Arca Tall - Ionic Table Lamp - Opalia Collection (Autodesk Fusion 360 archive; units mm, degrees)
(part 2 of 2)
create_component "CreateComponent4"
create_component "CreateComponent5"
create_component "CreateComponent6"
create_component "CreateComponent7"
create_component "CreateComponent8"
remove_body "RemoveBody1"
create_component "CreateComponent9"
create_component "CreateComponent10"
create_component "CreateComponent11"
create_component "CreateComponent12"
create_component "CreateComponent13"
create_component "CreateComponent14"
create_component "CreateComponent15"
create_component "CreateComponent16"
create_component "CreateComponent17"
create_component "CreateComponent18"
remove_body "RemoveBody6"
create_component "CreateComponent19"
create_component "CreateComponent20"
create_component "CreateComponent21"
create_component "CreateComponent22"
create_component "CreateComponent23"
named bodies: "Marble Base", "Rotary Switch", "Coiled - SVT (Blk Fabric)", "Glass Globe", "Metal Housing", "Metal Socket Cover", "Porcelain Socket", "Brass Dial - Dimmer Knob", "Solitaire Petite", "Facet Petite", "Body1", "Body2", "Plastic Insert", "Silicone Gasket", "Oculo Petite", "Balon v2", "Balon v3", "Trove - TL", "Trove - TL (1)", "Neoprene Pad", "2-Pole Plug End", "Rubber Grommet", "Chinois"

design "Trove - TL"
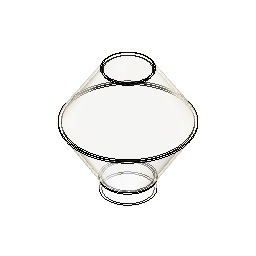
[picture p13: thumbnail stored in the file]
derived_base_feature "Derived Base Feature" bodies "Trove"
hole "Hole1" HoleDepth 88.9 HoleDiameter 44.45 TipAngle 118
sketch "Sketch1" plane through (0, 0, 0) normal (1, 0, 0) x axis (0, 1, 0)
  line L1 (0, 243.0601) -> (0, 247.8226)
  line L2 (-50.8, -12.7122) -> (-50.8, 10.9447)
  line L3 (0, -25.4) -> (0, 243.0601)
  line L4 (-46.0375, -12.7122) -> (-50.8, -12.7122)
  line L5 (-46.0375, -12.7122) -> (-46.0375, 12.3043)
  line L6 (-45.9716, 247.8226) -> (0, 247.8226)
  line L7 (-43.3841, 243.0601) -> (0, 243.0601)
  line L8 (-122.8321, 128.6352) -> (-51.757, 14.2971)
  line L9 (-117.1907, 128.5808) -> (-46.9945, 15.6567)
  line L10 (-48.6353, 246.3754) -> (-122.7993, 132.0392)
  line L11 (-46.0478, 241.6129) -> (-117.1579, 131.9848)
  arc A1 centre (-57.15, 10.9447) radius 6.35 clockwise from (-51.757, 14.2971) to (-50.8, 10.9447)
  arc A2 centre (-52.3875, 12.3043) radius 6.35 clockwise from (-46.9945, 15.6567) to (-46.0375, 12.3043)
  arc A3 centre (-114.4942, 130.257) radius 3.175 between (-117.1579, 131.9848) and (-117.1907, 128.5808)
  arc A4 centre (-120.1356, 130.3114) radius 3.175 between (-122.7993, 132.0392) and (-122.8321, 128.6352)
  arc A5 centre (-45.9716, 244.6476) radius 3.175 between (-45.9716, 247.8226) and (-48.6353, 246.3754)
  arc A6 centre (-43.3841, 239.8851) radius 3.175 clockwise from (-46.0478, 241.6129) to (-43.3841, 243.0601)
  point P3 (0, 247.8226)
  point P4 (0, 243.0601)
  vertical L1
  vertical L3
  tangent L5 A2
  perpendicular L1 L6
  perpendicular L1 L7
  tangent L11 A3
  tangent L9 A3
  tangent L10 A4
  tangent L8 A4
  equal A3 A4
  tangent L6 A5
  tangent L10 A5
  tangent L11 A6
  tangent L7 A6
  dimension "d8" distance P3 P4 = 4.7625
  dimension "d11" radius A2 = 6.35
  dimension "d15" radius A3 = 3.175
  dimension "d16" radius A5 = 3.175
  dimension "d17" radius A6 = 3.175
revolve "Revolve1" sketch "Sketch1" AlongAngle 180 bodies "Trove - TL"
revolve "Revolve2" sketch "Sketch1" AlongAngle -180
component_from_bodies "Body->Comp"
remove_body "RemoveBody2"
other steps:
base_feature "Base Feature" bodies "Trove - TL"
create_component "CreateComponent1"
remove_body "RemoveBody1"
named bodies: "Trove", "Trove - TL"

design "T9-5In"
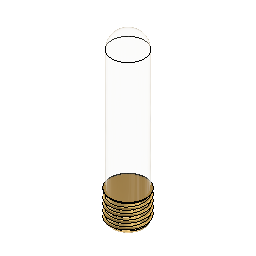
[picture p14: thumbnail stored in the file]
sketch "Sketch1" plane through (0, 0, 0) normal (0, 1, 0) x axis (1, 0, 0)
  line L1 (0, 0) -> (0, -127)
  line L2 (12.7, -127) -> (-12.7, -127)
  line L3 (12.7, -12.7) -> (12.7, -127)
  line L4 (-12.7, -127) -> (-12.7, -12.7)
  arc A1 centre (0, -12.7) radius 12.7 clockwise from (-12.7, -12.7) to (12.7, -12.7)
  point P1 (0, 0)
  point P3 (0, 0)
  coincident P1 P3
  vertical L1
  horizontal L2
  vertical L3
  vertical L4
revolve "Revolve1" sketch "Sketch1" AlongAngle 360 bodies "BU-T10-5-LED-120V"
derived_base_feature "Derived Base Feature" bodies "E26 Base"
move "Move1"
component_from_bodies "Body->Comp"
copy_paste "CutPaste"
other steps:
base_feature "Base Feature" bodies "BU-T10-5-LED-120V"
create_component "CreateComponent1"
create_component "CreateComponent2"
remove_body "RemoveBody1"
remove_instance "RemoveInstance1"
named bodies: "BU-T10-5-LED-120V", "E26 Base"

design "Balon v2"
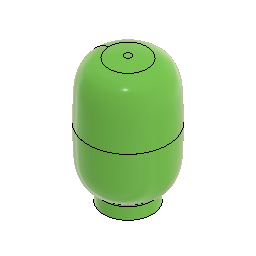
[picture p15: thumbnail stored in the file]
derived_base_feature "Derived Base Feature" bodies "Balon"
work_plane "WorkPlane1" AlongDistance 0
sketch "Sketch1" plane through (0, 0, 0) normal (0, 1, 0) x axis (1, 0, 0)
  line L1 (0, 317.5) -> (0, 2.9083)
  curve K1 (-82.9821, 124.2212) -> (-50.8, 237.8015)
  curve K2 (-51.0925, 237.681) -> (-50.8, 237.8015)
  curve K3 (-51.3855, 237.5558) -> (-51.0925, 237.681)
  curve K4 (-54.7608, 236.0513) -> (-51.3855, 237.5558)
  curve K5 (-57.9615, 234.05) -> (-54.7608, 236.0513)
  curve K6 (-67.2727, 226.749) -> (-57.9615, 234.05)
  curve K7 (-69.0552, 224.2615) -> (-67.2727, 226.749)
  curve K8 (-72.1872, 218.7832) -> (-69.0552, 224.2615)
  curve K9 (-74.1213, 215.1556) -> (-72.1872, 218.7832)
  curve K10 (-78.3031, 204.3965) -> (-74.1213, 215.1556)
  curve K11 (-79.7275, 197.3397) -> (-78.3031, 204.3965)
  curve K12 (-81.3333, 185.4664) -> (-79.7275, 197.3397)
  curve K13 (-81.6254, 178.4008) -> (-81.3333, 185.4664)
  curve K14 (-82.49, 152.2133) -> (-81.6254, 178.4008)
  curve K15 (-82.9821, 136.067) -> (-82.49, 152.2133)
  curve K16 (-82.9821, 124.2212) -> (-82.9821, 136.067)
  curve K17 (50.8, 237.7999) -> (82.9821, 124.2212)
  curve K18 (82.9821, 140.3031) -> (82.9821, 124.2212)
  curve K19 (81.9353, 169.4257) -> (82.9821, 140.3031)
  curve K20 (81.3621, 183.6489) -> (81.9353, 169.4257)
  curve K21 (80.9478, 189.8724) -> (81.3621, 183.6489)
  curve K22 (77.8147, 206.9858) -> (80.9478, 189.8724)
  curve K23 (74.9652, 213.2153) -> (77.8147, 206.9858)
  curve K24 (69.4688, 224.1531) -> (74.9652, 213.2153)
  curve K25 (67.2512, 226.458) -> (69.4688, 224.1531)
  curve K26 (61.5696, 231.3138) -> (67.2512, 226.458)
  curve K27 (57.377, 234.6711) -> (61.5696, 231.3138)
  curve K28 (52.0556, 237.2628) -> (57.377, 234.6711)
  curve K29 (51.4313, 237.5413) -> (52.0556, 237.2628)
  curve K30 (50.8, 237.7999) -> (51.4313, 237.5413)
  line L2 (-50.8, 317.5) -> (-50.8, 237.8015)
  line L3 (50.8, 317.5) -> (50.8, 237.7999)
  line L4 (-19.0713, 6.7501) -> (-19.0713, 6.7501)
  curve K31 (82.9821, 124.1958) -> (40.1509, 7.3012)
  curve K32 (41.8198, 7.6176) -> (40.1509, 7.3012)
  curve K33 (43.2113, 8.0663) -> (41.8198, 7.6176)
  curve K34 (47.0139, 9.2854) -> (43.2113, 8.0663)
  curve K35 (47.3314, 9.3805) -> (47.0139, 9.2854)
  curve K36 (50.1192, 10.3272) -> (47.3314, 9.3805)
  curve K37 (51.833, 11.0085) -> (50.1192, 10.3272)
  curve K38 (57.8313, 14.1895) -> (51.833, 11.0085)
  curve K39 (61.4491, 17.0488) -> (57.8313, 14.1895)
  curve K40 (66.8203, 21.5867) -> (61.4491, 17.0488)
  curve K41 (68.5372, 23.5528) -> (66.8203, 21.5867)
  curve K42 (71.2201, 27.8971) -> (68.5372, 23.5528)
  curve K43 (74.7424, 33.8984) -> (71.2201, 27.8971)
  curve K44 (78.2342, 44.8406) -> (74.7424, 33.8984)
  curve K45 (79.6792, 50.3463) -> (78.2342, 44.8406)
  curve K46 (81.3558, 63.5576) -> (79.6792, 50.3463)
  curve K47 (81.6386, 70.4415) -> (81.3558, 63.5576)
  curve K48 (82.4897, 96.2198) -> (81.6386, 70.4415)
  curve K49 (82.9814, 112.3523) -> (82.4897, 96.2198)
  curve K50 (82.9821, 124.1958) -> (82.9814, 112.3523)
  curve K51 (-40.1501, 7.301) -> (-82.9821, 124.1958)
  curve K52 (-82.9813, 110.5256) -> (-82.9821, 124.1958)
  curve K53 (-82.2545, 88.8594) -> (-82.9813, 110.5256)
  curve K54 (-81.6277, 70.519) -> (-82.2545, 88.8594)
  curve K55 (-81.3572, 64.3441) -> (-81.6277, 70.519)
  curve K56 (-79.4149, 46.8924) -> (-81.3572, 64.3441)
  curve K57 (-76.5204, 38.9768) -> (-79.4149, 46.8924)
  curve K58 (-73.5142, 32.2947) -> (-76.5204, 38.9768)
  curve K59 (-72.5556, 30.3818) -> (-73.5142, 32.2947)
  curve K60 (-69.7914, 25.3691) -> (-72.5556, 30.3818)
  curve K61 (-68.3824, 23.4028) -> (-69.7914, 25.3691)
  curve K62 (-64.5419, 19.5456) -> (-68.3824, 23.4028)
  curve K63 (-62.3002, 17.7646) -> (-64.5419, 19.5456)
  curve K64 (-53.6583, 11.1976) -> (-62.3002, 17.7646)
  curve K65 (-49.6968, 10.1396) -> (-53.6583, 11.1976)
  curve K66 (-43.4141, 8.1331) -> (-49.6968, 10.1396)
  curve K67 (-41.9704, 7.6516) -> (-43.4141, 8.1331)
  curve K68 (-40.1963, 7.3098) -> (-41.9704, 7.6516)
  curve K69 (-40.1732, 7.3054) -> (-40.1963, 7.3098)
  curve K70 (-40.1501, 7.301) -> (-40.1732, 7.3054)
  line L5 (-82.9821, 124.1958) -> (-82.9821, 124.2212)
  line L6 (82.9821, 124.2212) -> (82.9821, 124.1958)
  line L7 (0, 317.5) -> (-50.8, 317.5)
  line L8 (7.2015, 3.048) -> (0, 3.048)
  line L9 (0, 3.048) -> (-7.2015, 3.048)
  arc A1 centre (0, 188.595) radius 185.6867 clockwise from (-7.2015, 3.048) to (-40.1502, 7.301)
  arc A2 centre (0, 188.595) radius 185.6867 clockwise from (40.151, 7.3012) to (7.2015, 3.048)
  point P38 (-40.1502, 7.301)
  point P43 (40.1509, 7.3012)
  point P62 (-40.1501, 7.301)
  point P81 (40.151, 7.3012)
  point P84 (0, 3.048)
  vertical L1
  horizontal L4
  coincident P38 K51
  symmetric L1 A1 A2
  coincident A2 P43
  coincident A1 P62
  coincident K31 P81
  perpendicular L2 L7
  horizontal L8
  coincident L1 P84
  horizontal L9
revolve "Revolve1" sketch "Sketch1" AlongAngle 360
shell "Shell1" innerThickness 3.81
fillet "Fillet1" radius 6.35
offset_faces "OffsetFaces1" distance -50.8
move "Move1"
move "Move2"
component_from_bodies "Body->Comp1"
component_from_bodies "Body->Comp2"
sketch "Sketch2" plane through (0, 0, 0) normal (0, 1, 0) x axis (1, 0, 0)
  line L1 (-85.5221, 124.2212) -> (-85.5221, 124.1961)
  curve K1 (-58.9057, 236.4383) -> (-50.8, 241.7989)
  curve K2 (-50.8, 241.554) -> (-50.8, 241.7989)
  curve K3 (-50.904, 240.933) -> (-50.8, 241.554)
  curve K4 (-51.2936, 240.2837) -> (-50.904, 240.933)
  curve K5 (-51.734, 239.7561) -> (-51.2936, 240.2837)
  curve K6 (-53.328, 238.5038) -> (-51.734, 239.7561)
  curve K7 (-54.0892, 238.1997) -> (-53.328, 238.5038)
  curve K8 (-58.9057, 236.4383) -> (-54.0892, 238.1997)
  curve K9 (-89.3309, 124.2212) -> (-58.9057, 236.4383)
  curve K10 (-62.6336, 234.9735) -> (-58.9057, 236.4383)
  curve K11 (-65.581, 233.1032) -> (-62.6336, 234.9735)
  curve K12 (-73.0224, 227.0019) -> (-65.581, 233.1032)
  curve K13 (-74.8981, 224.836) -> (-73.0224, 227.0019)
  curve K14 (-78.1104, 219.6097) -> (-74.8981, 224.836)
  curve K15 (-80.2663, 215.561) -> (-78.1104, 219.6097)
  curve K16 (-84.0943, 205.8277) -> (-80.2663, 215.561)
  curve K17 (-85.4655, 200.1154) -> (-84.0943, 205.8277)
  curve K18 (-87.4092, 188.5789) -> (-85.4655, 200.1154)
  curve K19 (-87.7349, 182.3889) -> (-87.4092, 188.5789)
  curve K20 (-88.4233, 165.9645) -> (-87.7349, 182.3889)
  curve K21 (-89.328, 138.6964) -> (-88.4233, 165.9645)
  curve K22 (-89.3309, 124.2212) -> (-89.328, 138.6964)
  line L2 (-89.3309, 124.1958) -> (-89.3309, 124.2212)
  curve K23 (-46.5001, 7.301) -> (-89.3309, 124.1958)
  curve K24 (-89.3314, 112.4293) -> (-89.3309, 124.1958)
  curve K25 (-88.8181, 95.3068) -> (-89.3314, 112.4293)
  curve K26 (-88.346, 81.2892) -> (-88.8181, 95.3068)
  curve K27 (-88.0298, 70.4902) -> (-88.346, 81.2892)
  curve K28 (-87.1514, 58.328) -> (-88.0298, 70.4902)
  curve K29 (-86.3326, 50.6119) -> (-87.1514, 58.328)
  curve K30 (-81.0932, 33.6688) -> (-86.3326, 50.6119)
  curve K31 (-77.3163, 27.4309) -> (-81.0932, 33.6688)
  curve K32 (-74.8955, 23.6666) -> (-77.3163, 27.4309)
  curve K33 (-73.5108, 22.0741) -> (-74.8955, 23.6666)
  curve K34 (-70.2346, 19.0457) -> (-73.5108, 22.0741)
  curve K35 (-64.8094, 14.3548) -> (-70.2346, 19.0457)
  curve K36 (-56.6696, 10.3041) -> (-64.8094, 14.3548)
  curve K37 (-54.0053, 9.483) -> (-56.6696, 10.3041)
  curve K38 (-49.1487, 7.9411) -> (-54.0053, 9.483)
  curve K39 (-48.3482, 7.6526) -> (-49.1487, 7.9411)
  curve K40 (-46.5001, 7.301) -> (-48.3482, 7.6526)
  line L3 (0, 266.7) -> (0, 0)
  line L4 (0, 3.048) -> (-7.7894, 3.048)
  line L5 (-50.8, 266.7) -> (-50.8, 241.7989)
  line L6 (0, 266.7) -> (-50.8, 266.7)
  arc A1 centre (-6.9779, 188.7329) radius 185.6867 clockwise from (-7.7894, 3.048) to (-46.5001, 7.301)
  point P1 (0, 0)
  point P44 (0, 0)
  point P46 (0, 3.048)
  point P5 (-50.8, 241.554)
  point P49 (0, 266.7)
  coincident P1 P44
  coincident L3 P46
  coincident P5 L5
  coincident L3 P49
revolve "Revolve2" sketch "Sketch2" AlongAngle 360 bodies "Balon v3"
shell "Shell2" innerThickness 3.81
component_from_bodies "Body->Comp3"
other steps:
base_feature "Base Feature1" bodies "Balon"
base_feature "Base Feature1" bodies "Balon v3"
base_feature "Base Feature1" bodies "Balon v2"
create_component "CreateComponent1"
remove_body "RemoveBody1"
create_component "CreateComponent2"
remove_body "RemoveBody2"
create_component "CreateComponent3"
remove_body "RemoveBody3"
named bodies: "Balon", "Balon v2", "Balon v3"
